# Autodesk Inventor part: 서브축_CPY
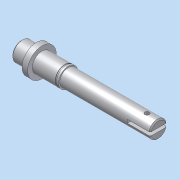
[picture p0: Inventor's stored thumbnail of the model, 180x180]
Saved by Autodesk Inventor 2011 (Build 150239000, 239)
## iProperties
Created: 2014-12
Part Number: 서브축_CPY
Document SubType Name: Modeling
Designer: SDA
Mass: 23.2871 g
Surface Area: 76.512 cm^2
Volume: 23.2871 cm^3
Density: 1 g/cm^3
Company: 한국ATC센터
Author: KYOUNG IL JANG
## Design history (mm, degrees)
sketch "스케치1"
  geometry: L1 (0, 0)-(120, 0); L2 (0, 0)-(0, 7.5); L3 (1, 8.5)-(13, 8.5); L4 (13, 8.5)-(13, 12.5); L5 (13, 12.5)-(18, 12.5); L6 (18, 12.5)-(18, 8.5); L7 (18, 8.5)-(41, 8.5); L8 (120, 7.5)-(120, 0); L9 (0, 7.5)-(1, 8.5); L10 (41, 8.5)-(41, 7.5); L11 (41, 7.5)-(120, 7.5); 1 further point
  constraints: 22 end point, 3 parallel, 3 perpendicular, 2 collinear, 2 point on line, 2 vertical, 1 horizontal
  dimensions: "d0" = 5 distance of L4.end L5.end; "d1" = 17 diameter of L7 L1; "d2" = 13 distance of point (0, 8.5) L3.end; "d3" = 25 diameter of L5 L1; "d4" = 120 distance of L1.start L1.end; "d5" = 1 distance of L2.end point (0, 8.5); "d6" = 1 distance of L3.start point (0, 8.5) (= d5); "d15" = 15 diameter of L11 L1; "d16" = 23 distance of L6.end L7.end
revolve "회전1" sketch "스케치1" stored, may be unused: angle "d9" = 90 deg
node "작업 평면1"
sketch "스케치2"
  geometry: L1 (11.5, 12.5)-(11.5, -12.5) reference; L2 (-3, 2.5)-(6, 2.5); L3 (6, -2.5)-(-3, -2.5); A1 r 2.5 centre (6, 0) between (6, -2.5) and (6, 2.5); A2 r 2.5 centre (-3, 0) between (-3, 2.5) and (-3, -2.5); 1 further point
  constraints: 4 end point, 4 point on circle, 4 tangent, 2 centre point, 1 horizontal alignment, 1 parallel, 1 perpendicular
  dimensions: "d10" = 5 distance between parallel lines of L3 L2; "d11" = 14 dimension on A1 A2; "d12" = 3 distance edge to line of A1 L1
extrude "돌출1" cut sketch "스케치2" distance "d13" = 3; taper "d14" = 0 deg
sketch "스케치3"
  geometry: L1 (18, -12.5)-(18, 12.5) reference; L2 (13, -12.5)-(13, 12.5) reference; L3 (18, 8.5)-(41, 8.5) reference; L4 (38, 8.5)-(39.15, 8.5); L5 (39.15, 8.5)-(39.15, 8.1); L6 (39.15, 8.1)-(38, 8.1); L7 (38, 8.1)-(38, 8.5); L8 (-24, 0)-(144, 0) reference; 1 further point
  constraints: 8 end point, 2 parallel, 1 horizontal, 1 perpendicular, 1 point on line
  dimensions: "d17" = 20 distance between parallel lines of L7 L1; "d18" = 1.15 distance of L5.end L6.end; "d19" = 8.1 distance between parallel lines of L6 L8
revolve "회전2" sketch "스케치3" stored, may be unused: angle "d20" = 90 deg
chamfer "모따기1" distance "d21" = 1; stored, may be unused: second distance "d22" = 2, angle "d23" = 45 deg
sketch "스케치4"
  geometry: L1 (-120, 1.5)-(-100, 1.5); L2 (-100, 1.5)-(-100, -1.5); L3 (-100, -1.5)-(-120, -1.5); L4 (-120, -1.5)-(-120, 1.5); L5 (-120, -6.5)-(-120, 6.5) reference; 2 further points
  constraints: 8 end point, 2 parallel, 1 collinear, 1 horizontal, 1 horizontal alignment, 1 midpoint, 1 perpendicular
  dimensions: "d24" = 3 distance between parallel lines of L3 L1; "d25" = 20 distance of L2.end L3.end
extrude "돌출2" cut sketch "스케치4" stored distance "d26" = 10; taper "d27" = 0 deg
sketch "스케치5"
  geometry: L1 (120, 6.325)-(120, -6.325) reference; C1 r 2 at (110, 0); 1 further point
  constraints: 1 centre point, 1 horizontal alignment
  dimensions: "d28" = 4 diameter of C1; "d29" = 10 distance from line of L1 C1.centre
extrude "돌출3" cut sketch "스케치5" stored distance "d30" = 10; taper "d31" = 0 deg
node "솔리드1"
node "투영된 루프1"
